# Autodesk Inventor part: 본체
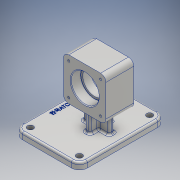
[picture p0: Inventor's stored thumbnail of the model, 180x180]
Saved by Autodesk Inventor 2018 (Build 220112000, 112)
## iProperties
Created: 2020-11
Part Number: 본체
Material: 알루미늄 6061
Document SubType Name: Modeling
Designer: USER
Density: 2.7 g/cm^3
Appearance: 알루미늄 - 평지
Mass: 683.214 g
Surface Area: 542.794 cm^2
Volume: 253.042 cm^3
Author: USER
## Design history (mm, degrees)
sketch "스케치1"
  geometry: L1 (-49, -65)-(49, -65); L2 (49, -65)-(49, 65); L3 (49, 65)-(-49, 65); L4 (-49, 65)-(-49, -65); L5 (-49, -65)-(49, 65); L6 (49, -65)-(-49, 65); 1 further point
  constraints: 12 end point, 2 midpoint, 2 parallel, 1 horizontal, 1 perpendicular
  dimensions: "d0" = 98 distance of L3.end L2.end; "d1" = 130 distance of L2.end L1.end
extrude "돌출1" new body sketch "스케치1" distance "d2" = 10; taper "d3" = 0 deg
fillet "모깎기1" dims "d4" = 12
fillet "모깎기2" dims "d5" = 3
sketch "스케치2"
  geometry: L1 (19, 38)-(-45, 38); L2 (-45, 38)-(-45, 102); L3 (-45, 102)-(19, 102); L4 (19, 102)-(19, 38); L5 (19, 38)-(-45, 102); L6 (-45, 38)-(19, 102); L7 (-13, 102)-(-13, 38); L8 (49, 7)-(49, 0) reference; L9 (19, 70)-(-45, 70); L10 (37, 0)-(-37, 0) reference; 2 further points
  constraints: 16 end point, 6 midpoint, 2 parallel, 1 horizontal, 1 perpendicular
  dimensions: "d6" = 64 distance of L2.end L3.end; "d7" = 64 distance of L1.end L2.end; "d8" = 62 distance between parallel lines of L8 L7; "d9" = 70 distance between parallel lines of L9 L10
extrude "돌출2" join sketch "스케치2" stored distance "d10" = 42; taper "d11" = 0 deg
fillet "모깎기3" dims "d12" = 8
sketch "스케치3"
  geometry: L1 (-7, 4)-(33, 4); L2 (33, 4)-(33, -4); L3 (33, -4)-(-7, -4); L4 (-7, -4)-(-7, 4); L5 (13, 4)-(13, -4); L6 (-7, 0)-(33, 0); L7 (-49, 53)-(-49, -53) reference; L8 (37, 65)-(-37, 65) reference; 1 further point
  constraints: 12 end point, 4 midpoint, 2 parallel, 1 horizontal, 1 perpendicular
  dimensions: "d13" = 62 distance between parallel lines of L7 L5; "d14" = 65 distance between parallel lines of L8 L6; "d15" = 8 distance of L3.end L1.start; "d16" = 40 distance of L1.start L1.end
extrude "돌출3" join sketch "스케치3" stored distance "d17" = 42; taper "d18" = 0 deg
sketch "스케치4"
  geometry: L1 (9, 17)-(17, 17); L2 (17, 17)-(17, -17); L3 (17, -17)-(9, -17); L4 (9, -17)-(9, 17); L5 (9, 0)-(17, 0); L6 (13, -17)-(13, 17); L7 (-49, 53)-(-49, -53) reference; L8 (37, 65)-(-37, 65) reference; 1 further point
  constraints: 12 end point, 4 midpoint, 2 parallel, 1 horizontal, 1 perpendicular
  dimensions: "d19" = 62 distance between parallel lines of L7 L6; "d20" = 65 distance between parallel lines of L8 L5; "d21" = 8 distance of L1.start L1.end; "d22" = 34 distance of L1.end L2.end
extrude "돌출4" join sketch "스케치4" stored distance "d23" = 42; taper "d24" = 0 deg
fillet "모깎기4" dims "d25" = 3
fillet "모깎기5" dims "d26" = 3
fillet "모깎기6" dims "d27" = 3
sketch "스케치5"
  geometry: L1 (37, 102)-(-11, 102) reference; L2 (-19, 94)-(-19, 46) reference; C1 r 21 at (13, 70); 3 further points
  constraints: 2 midpoint, 1 centre point, 1 horizontal alignment, 1 vertical alignment
  dimensions: "d28" = 42 diameter of C1
extrude "돌출5" cut sketch "스케치5" distance "d29" = 15; taper "d30" = 0 deg
sketch "스케치6"
  geometry: C1 r 21 at (0, 0) reference; C2 r 18 at (0, 0); 1 further point
  constraints: 1 centre point, 1 coincident
  dimensions: "d31" = 36 diameter of C2
extrude "돌출6" cut sketch "스케치6" extent not by distance; stored distance "d32" = 15; taper "d33" = 0 deg
fillet "모깎기7" dims "d34" = 0.3
fillet "모깎기8" dims "d35" = 0.3
chamfer "모따기1" distance "d36" = 1; stored, may be unused: second distance "d37" = 2, angle "d38" = 45 deg
chamfer "모따기2" distance "d39" = 1; stored, may be unused: second distance "d40" = 2, angle "d41" = 45 deg
sketch "스케치7"
  geometry: A1 r 8 centre (-11, 94) between (-11, 102) and (-19, 94) reference; A2 r 8 centre (-11, 46) between (-19, 46) and (-11, 38) reference; A3 r 8 centre (37, 46) between (37, 38) and (45, 46) reference; A4 r 8 centre (37, 94) between (45, 94) and (37, 102) reference; 5 further points
  constraints: 4 coincident
hole "구멍1" sketch "스케치7" at (-11, 94), (-11, 46), (37, 46), (37, 94) diameter "d42" = 3.242; stored, may be unused: countersink angle "d46" = 90 deg, drill point angle "d48" = 118 deg; dims "d43" = 8, "d44" = 4, "d45" = 2, "d47" = 10
sketch "스케치8"
  geometry: A1 r 12 centre (-37, 53) between (-37, 65) and (-49, 53) reference; A2 r 12 centre (-37, -53) between (-49, -53) and (-37, -65) reference; A3 r 12 centre (37, -53) between (37, -65) and (49, -53) reference; A4 r 12 centre (37, 53) between (49, 53) and (37, 65) reference; 5 further points
  constraints: 4 coincident
hole "구멍2" sketch "스케치8" at (-37, 53), (-37, -53), (37, -53), (37, 53) diameter "d49" = 9; stored, may be unused: countersink angle "d53" = 90 deg, drill point angle "d55" = 118 deg; dims "d50" = 8, "d51" = 4, "d52" = 2, "d54" = 10
sketch "스케치9"
  geometry: L1 (37, 65)-(-37, 65) reference; L2 (-49, 53)-(-49, -53) reference; 2 further points
  constraints: 1 other
  dimensions: "d56" = 65 distance from line of L1 point (-39, 0); "d57" = 10 distance from line of point (-39, 0) L2
feature "엠보싱1" sketch "스케치9" dims "d0" = 98, "d1" = 130, "d6" = 64, "d7" = 64, "d8" = 62, "d9" = 70, "d58" = 0.5, "d59" = 0
node "솔리드1"
mirror "미러1"
mirror "미러2"
